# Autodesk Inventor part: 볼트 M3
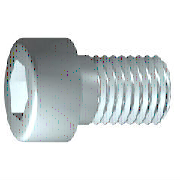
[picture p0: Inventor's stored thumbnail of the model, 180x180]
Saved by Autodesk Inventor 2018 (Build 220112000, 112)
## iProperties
IsCustomPart: 0
Created: 2012-02
Part Number: 볼트 M3
Material: 스테인리스강
Description: 6각 소켓 머리 캡 나사
Document SubType Name: Modeling
Standard: ISO 4762
Designer: mduedu
Standard Revision: Fourth edition 2004-03-01
Standards Organization: ISO
Language: ko-KR
Size Designation: M3 x 8
Categories: <MemberInstance><Categories><Category DisplayName="조임쇠" InternalName="e4da775c-781d-43d5-af7c-5136215cf5a6" Mnemonic="FSTN"><Category DisplayName="볼트" InternalN
Density: 7.75 g/cm^3
Appearance: 반광택
Author: mduedu
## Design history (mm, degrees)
sketch "스케치1"
  geometry: L1 (-0.867, 0)-(8, 0); L2 (8, 0)-(8, 1.5); L3 (8, 1.5)-(1.25, 1.5); L4 (1.25, 1.5)-(0.943, 1.5); L5 (0.943, 1.5)-(0, 1.5); L6 (0, 1.5)-(0, 2.75); L7 (0, 2.75)-(-3, 2.75); L8 (-3, 2.75)-(-3, 1.443); L9 (-3, 1.443)-(-1.7, 1.443); L10 (-1.7, 1.443)-(-0.867, 0); L11 (-5.2, 0)-(10.2, 0) reference; L12 (0, -0.55)-(0, 3.3) reference; L13 (1.25, 1.5)-(0, 1.5)
  constraints: 22 end point, 6 parallel, 2 collinear, 2 perpendicular, 1 horizontal, 1 point on line
  dimensions: "d1" = 6.75 distance from line of L3.end L2 (= GEL); "d2" = 0.30683 distance of L4.end L3.end (computed from GAL); "d3" = 3 distance between parallel lines of L8 L6 (= KOH); "d4" = 1.3 distance of L8.end L9.end (= INTI); "d5" = 60 deg angle of L10 L1; "d6" = 3 diameter of L3 L1 (= GD); "d7" = 3 diameter of L5 L1 (= BDM); "d8" = 2.88675 diameter of L9 L1 (= 1.1547 x SW); "d9" = 5.5 diameter of L7 L1 (= KOD); "d26" = 8 distance between parallel lines of L12 L2 (= NLG)
revolve "본체" sketch "스케치1" stored, may be unused: angle "d10" = 90 deg
sketch "스케치2"
  geometry: L1 (0, -3.85)-(0, 3.85) reference; L2 (-3.85, 0)-(3.85, 0) reference; L3 (1.443, 0)-(0.722, -1.25); L4 (0.722, -1.25)-(-0.722, -1.25); L5 (-0.722, -1.25)-(-1.443, 0); L6 (-1.443, 0)-(-0.722, 1.25); L7 (-0.722, 1.25)-(0.722, 1.25); L8 (0.722, 1.25)-(1.443, 0); 2 further points
  constraints: 12 end point, 1 coincident, 1 horizontal alignment, 1 point on line, 12 other
extrude "슬롯" join sketch "스케치2" stored distance "d11" = 10; taper "d12" = 0 deg
workplane "Work Plane1"
fillet "Fillet2" dims "d30" = 0.1 (= R)
body "Solid1"
fillet "모깎기1" dims "d17" = 0.3 (= RR)
feature "스레드" dims "d13" = 6.75 (= GEL), "d14" = 0
chamfer "모따기1" distance "d15" = 0.30673 (= -0.5 x SPD + 0.5 x GD); stored, may be unused: second distance "d16" = 0.30673 (= GUL), angle "d27" = 45 deg
other parameters: "GD" = 3 [user parameter; used in 2 equation terms], "NLG" = 8 [user parameter; used in 1 equation term], "GEL" = 6.75 [user parameter; used in 2 equation terms], "KOD" = 5.5 [user parameter; used in 1 equation term], "KOH" = 3 [user parameter; used in 1 equation term], "INTI" = 1.3 [user parameter; used in 1 equation term], "GAL" = 0.30673 (= 0.61345 x PTC) [user parameter; used in 1 equation term], "GUL" = 0.30673 (= 0.61345 x PTC) [user parameter; used in 1 equation term], "BDM" = 3 (= NND) [user parameter; used in 1 equation term], "SW" = 2.5 [user parameter; used in 2 equation terms], "RR" = 0.3 [user parameter; used in 1 equation term], "SPD" = 2.38655 (= NND - 1.2269 x PTC) [user parameter; used in 1 equation term], "d19" = 0, "d28" = 0, "d29" = 0, "R" = 0.1 [user parameter; used in 1 equation term], "TOA" = 30 deg [user parameter], "GD1" = 2.38655 (= THREADDIA - 1.2269 x PTC) [user parameter], "THREADDIA" = 3 [user parameter; used in 1 equation term], "FAWI" = 45 deg [user parameter], "PTC" = 0.5 [user parameter; used in 5 equation terms], "NND" = 3 [user parameter; used in 2 equation terms], "E0" = 2.8875 (= 1.155 x SW) [user parameter]
